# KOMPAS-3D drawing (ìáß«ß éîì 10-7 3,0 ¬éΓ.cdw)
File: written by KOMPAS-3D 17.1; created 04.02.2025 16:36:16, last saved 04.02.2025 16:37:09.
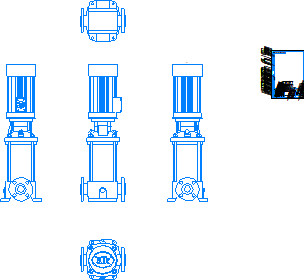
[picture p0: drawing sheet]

Sheet 1: A4, portrait

Title block, sheet 1: name: Насос ВМН 10-7 3,0 / кВт; designation: Насос ВМН 10-7 3,0 кВт; material: Сталь 10  ГОСТ 1050-2013; mass: 158,96; sheets: 1; sheet format: A4; stored path: \\adlc.lan\data\АДЛ_ПКД\3D-модели\ADL production\Насосы ГРАНПАМП\Насосы ВМН\ВМН10\KOMPAS 3D\Насос ВМН 10-7 3,0 кВт.cdw

Views: Вид 1, Спереди, Проекционный вид 2, Проекционный вид 3, Проекционный вид 4, Проекционный вид 5
Referenced files in \\adlc.lan\data\АДЛ_ПКД\3D-модели\ADL production\Насосы ГРАНПАМП\Насосы ВМН\ВМН10\KOMPAS 3D\: ВМН 10-7 3,0 кВт.m3d, Насос ВМН 10-7 3,0 кВт.m3d
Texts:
  Andrey
  АДЛ
Dimensions and other numbers on the sheet: 1:1; 1; 158,96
